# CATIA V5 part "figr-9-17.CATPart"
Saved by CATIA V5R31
Part number: Part1
Bounding box of the stored display mesh (mm): x -77.304 to 77.304, y -77.304 to 125.507, z 0 to 125
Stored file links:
  D:\PROJECTS\Project 2021\US EDITION\CATIA V5 6R 2021\Resources\Part Files\c09_catia_v5_6r2021_prt\c09_catia_v5_6r2021_prt\figr-9-17.CATPart
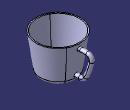
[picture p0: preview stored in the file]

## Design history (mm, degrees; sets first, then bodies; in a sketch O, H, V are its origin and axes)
Set1
  Plane1: type Normal, Curve Sketch3, RefPoint vertex of Sketch3
Body1 (main body)
  Sketch1 on yz-plane, origin (0, 0, 0), H (0, 1, 0), V (0, 0, 1)
    line L1 (0, 0) -> (60, 0)
    point P1 (60, 0)
    point P2 (60, 0)
    line L2 (60, 0) -> (77.5, 125)
    point P3 (77.5, 125)
    line L3 (77.5, 125) -> (0, 125)
    point P4 (0, 125)
    line L4 (0, 125) -> (0, 0)
    axis line L5 (0, 150.2858) -> (0, -31.0593)
    point P5 (0, 150.2858)
    radius about axis P1 L5 = 60
    radius about axis P3 L5 = 77.5
    distance L3 L1 = 125
    horizontal: L1 H, L3 H
    coincidence: P4 V, P2 P1, P5 V
    vertical: L4 V, L5 V
  Shaft1: profile Sketch1, axis Sketch1.L5, angle 360
  Fillet1: radius 15, on edge [face of Shaft1 | face of Shaft1]
  Shell1: ExtOffset 0, Face face of Shaft1, IntOffset 4
  Sketch2 on Plane1, origin (0, 62.9841, 0), H (-1, 0, 0), V (0, 0, 1)
    circle A1 centre (0, 22.002) radius 7.5
    reference projected point E1 (0, 22.002) from vertex of Sketch3
    radius A1 = 7.5
    concentricity: A1 E1
  Sketch3 on yz-plane, origin (0, 0, 0), H (0, 1, 0), V (0, 0, 1)
    line L1 (62.9841, 22.002) -> (78.2172, 22.002)
    arc A1 centre (78.2172, 44.1133) radius 22.1113 from (78.2172, 22.002) to (97.9307, 34.0988) ccw
    arc A2 centre (-112.3295, 140.9107) radius 235.8349 from (97.9307, 34.0988) to (117.8681, 89.6549) ccw
    arc A3 centre (104.0328, 92.7355) radius 14.1742 from (117.8681, 89.6549) to (104.4272, 106.9041) ccw
    arc A4 centre (93.6744, -279.4123) radius 386.4661 from (104.4272, 106.9041) to (82.9216, 106.9041) ccw
    horizontal: L1 H
    tangency: A1 L1, A2 A1, A3 A2, A4 A3
  Rib1: profile Sketch2, centre curve Sketch3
